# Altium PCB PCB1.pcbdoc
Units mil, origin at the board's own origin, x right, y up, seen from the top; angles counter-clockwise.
Board outline 1958.5 x 1420 mil, 2 copper layers (Top Layer, Bottom Layer); 4 components, 12 nets, 34 pads, 9 vias.
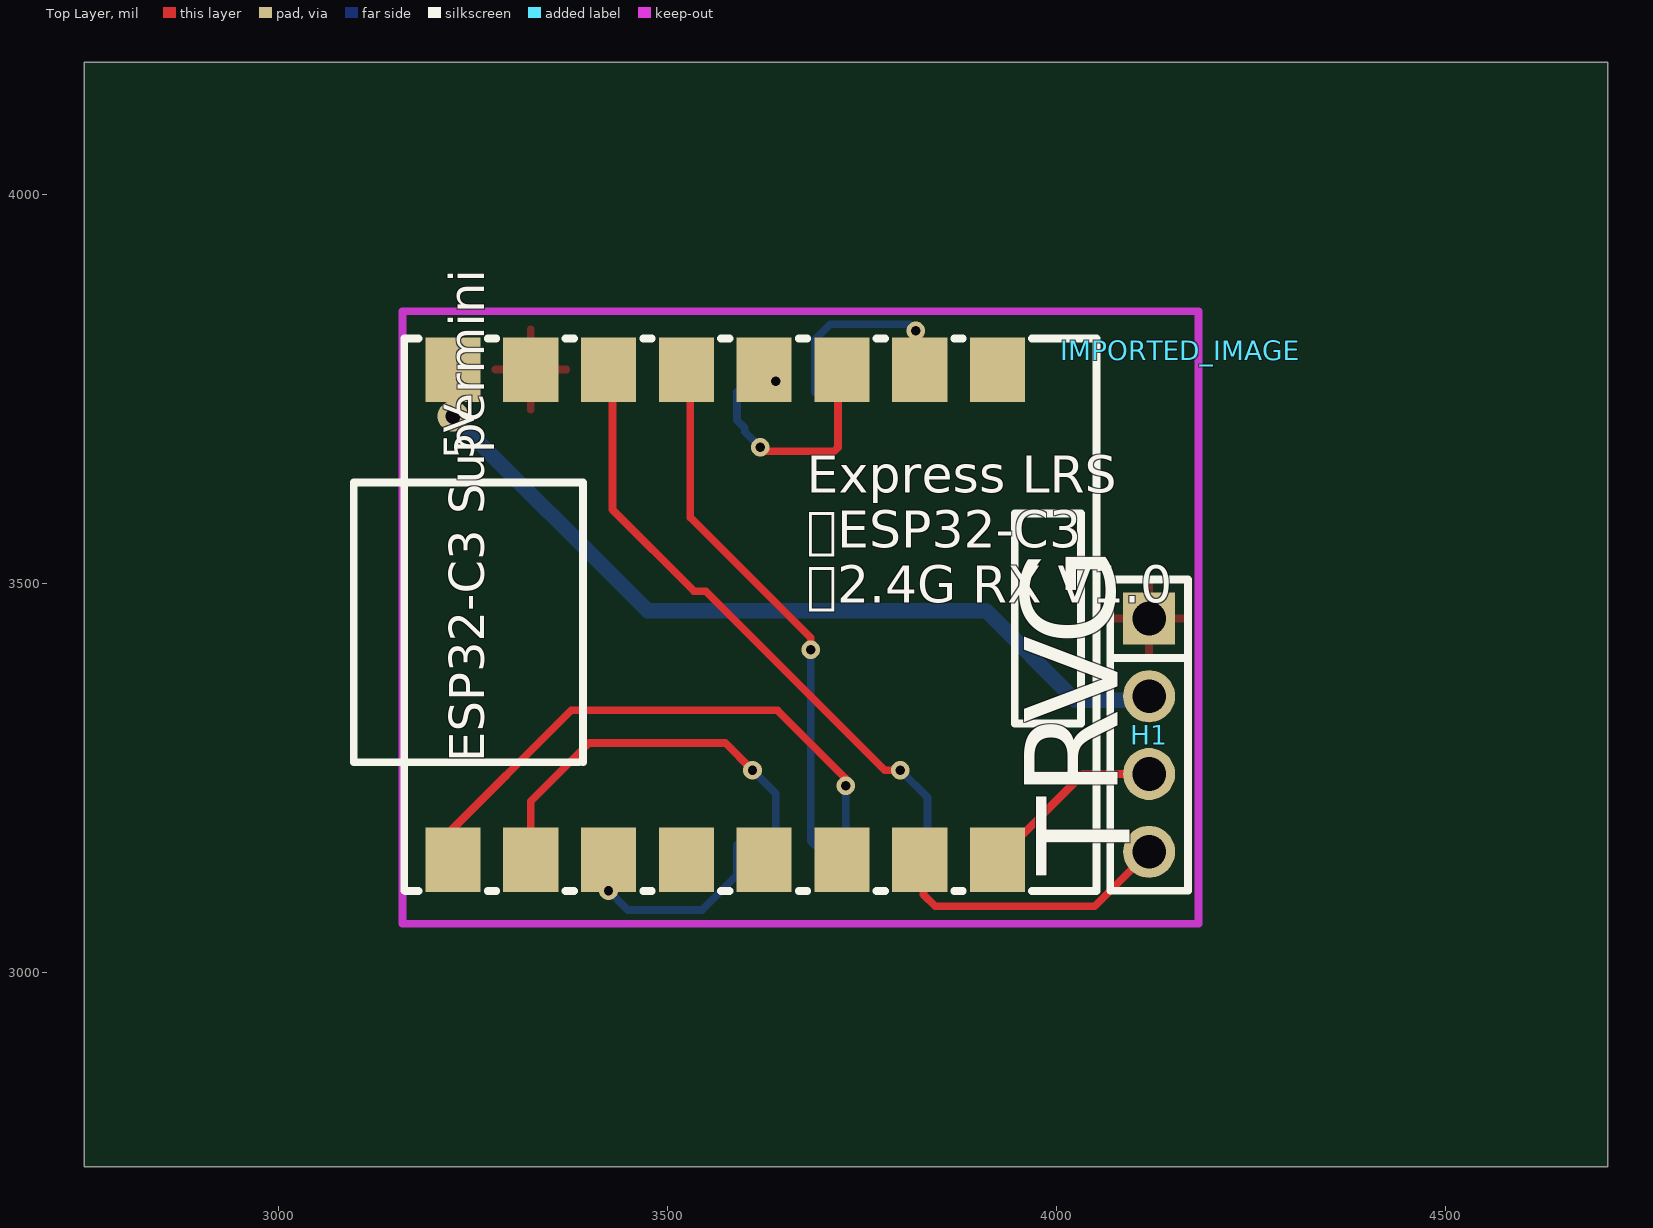
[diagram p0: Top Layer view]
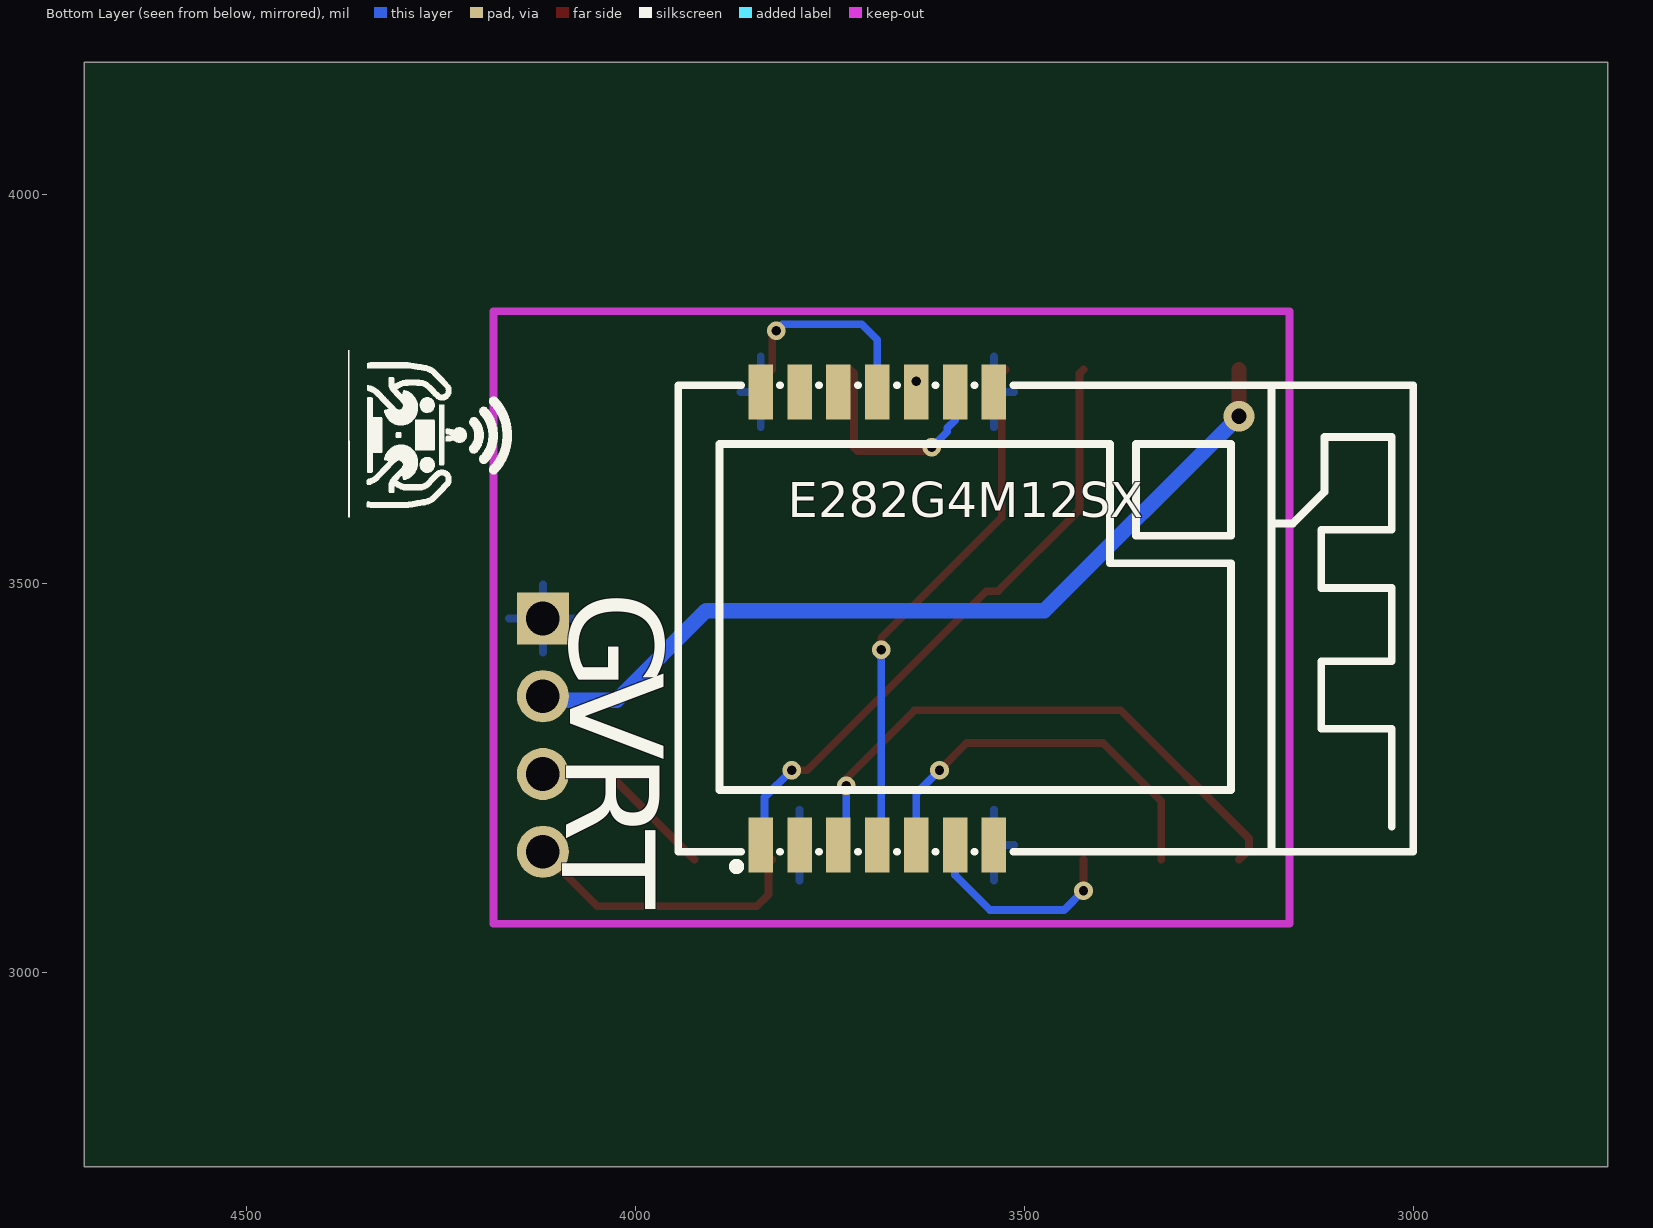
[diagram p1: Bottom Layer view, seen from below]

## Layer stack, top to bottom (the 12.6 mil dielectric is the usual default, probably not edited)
Top Layer: signal copper (thickness not stored)
Dielectric: dielectric 12.6, FR-4, Dk 4.8
Bottom Layer: signal copper (thickness not stored)

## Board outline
4708.5,2750 2750,2750 2750,4170 4708.5,4170

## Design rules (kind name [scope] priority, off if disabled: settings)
BoardOutlineClearance copperThickness1oz [All] p0: genericclearance=10 ignorepadtopadclearanceinfootprint=FALSE except(0: Arc-SplitContinuation Track-SplitContinuation SMDPad-SplitContinuation THPad-SplitContinuation Via-SplitContinuation Fill-SplitContinuation Poly-SplitContinuation Region-SplitContinuation Text-SplitContinuation; 6: Track-CutoutEdge SMDPad-CutoutEdge THPad-CutoutEdge Via-CutoutEdge Region-CutoutEdge; 11.8: Track-OutlineEdge SMDPad-OutlineEdge THPad-OutlineEdge Via-OutlineEdge Fill-OutlineEdge Region-OutlineEdge Poly-OutlineEdge Text-OutlineEdge Fill-CutoutEdge)
BoardOutlineClearance copperThickness2oz [All] p0: genericclearance=10 ignorepadtopadclearanceinfootprint=FALSE except(0: Arc-SplitContinuation Track-SplitContinuation SMDPad-SplitContinuation THPad-SplitContinuation Via-SplitContinuation Fill-SplitContinuation Poly-SplitContinuation Region-SplitContinuation Text-SplitContinuation; 6: Track-CutoutEdge SMDPad-CutoutEdge THPad-CutoutEdge Via-CutoutEdge Region-CutoutEdge; 11.8: Track-OutlineEdge SMDPad-OutlineEdge THPad-OutlineEdge Via-OutlineEdge Fill-OutlineEdge Region-OutlineEdge Poly-OutlineEdge Text-OutlineEdge Fill-CutoutEdge)
Clearance copperThickness1oz [(InNet('GND') OR InNet('$1N903') OR InNet('$1N951') OR InNet('$1N925') OR InNet('$1N893') OR InNet('$1N939') OR InNet('$1N882') OR InNet('$1N919') OR InNet('$1N1958') OR InNet('+5V') OR InNet('$1N1061') OR InNet('$1N2472'))] p1: gap=7 ignorepadtopadclearanceinfootprint=FALSE except(4: Track-Track; 6: Track-SMDPad SMDPad-SMDPad Track-THPad SMDPad-THPad THPad-THPad Track-Via SMDPad-Via THPad-Via Via-Via SMDPad-Fill THPad-Fill Via-Fill Fill-Fill Track-Region SMDPad-Region THPad-Region Via-Region Region-Region Track-Poly SMDPad-Poly THPad-Poly Via-Poly Fill-Poly Region-Poly Poly-Poly Track-Text SMDPad-Text THPad-Text Via-Text Fill-Text Region-Text Poly-Text Text-Text; 6.9: Track-Hole SMDPad-Hole THPad-Hole Via-Hole Fill-Hole Region-Hole Poly-Hole Text-Hole Sheet-Hole; 11.8: Track-Fill Fill-Region Track-Sheet SMDPad-Sheet THPad-Sheet Via-Sheet Fill-Sheet Region-Sheet Poly-Sheet Text-Sheet)
Clearance copperThickness2oz [All] p1: gap=7 ignorepadtopadclearanceinfootprint=FALSE except(6: Track-SMDPad SMDPad-SMDPad Track-THPad SMDPad-THPad THPad-THPad Track-Via SMDPad-Via THPad-Via Via-Via SMDPad-Fill THPad-Fill Via-Fill Fill-Fill Track-Region SMDPad-Region THPad-Region Via-Region Region-Region Track-Poly SMDPad-Poly THPad-Poly Via-Poly Fill-Poly Region-Poly Poly-Poly Track-Text SMDPad-Text THPad-Text Via-Text Fill-Text Region-Text Poly-Text Text-Text; 6.9: Track-Hole SMDPad-Hole THPad-Hole Via-Hole Fill-Hole Region-Hole Poly-Hole Text-Hole Sheet-Hole; 8: Track-Track; 11.8: Track-Fill Fill-Region Track-Sheet SMDPad-Sheet THPad-Sheet Via-Sheet Fill-Sheet Region-Sheet Poly-Sheet Text-Sheet)
DiffPairsRouting differentialPair [All] p1: maxuncoupledlength=10 minlimit=6 maxlimit=6 mostfreqgap=6 toplayer_minwidth=5 toplayer_prefwidth=10 toplayer_maxwidth=100 bottomlayer_minwidth=5 bottomlayer_prefwidth=10 bottomlayer_maxwidth=100
PasteMaskExpansion pasteMaskExpansion [All] p1: expansion=0
PlaneConnect innerPlane [All] p1: planeconnectstyle=Relief reliefexpansion=20 reliefentries=4 reliefconductorwidth=10 reliefairgap=10
PolygonConnect copperRegion [All] p1: connectstyle=Relief reliefentries=4 reliefconductorwidth=10 polygonreliefangle="90 Angle" airgapwidth=10
RoutingVias viaSize [All] p1: viastyle="Through Hole" holewidth=12.0078 minholewidth=11.811 maxholewidth=248.0314 width=24.0158 minwidth=19.685 maxwidth=393.7008
SolderMaskExpansion solderMaskExpansion [All] p1: useseparateexpansions=TRUE expansion=2 expansionbottom=2
Width copperThickness1oz [All] p1: maxlimit=100 minlimit=5 preferedwidth=10
Width copperThickness2oz [All] p1: maxlimit=100 minlimit=8 preferedwidth=10

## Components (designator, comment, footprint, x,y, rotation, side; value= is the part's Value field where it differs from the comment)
E282G4M12SX "E28-2G4M12S" WIRELM-SMD_E28-2G4M12S 3688.98,3455 r90 bottom
"ESP32-C3 Supermini" "ESP32C3-SuperMini" COMM-SMD_16P-L22.5-W18.0-P2.54-TL 3573.98,3460 r90 top
H1 "PZ254V-11-04P" HDR-TH_4P-P2.54-V-M 4118.98,3305 r270 top
IMPORTED_IMAGE "IMPORTED_IMAGE" IMPORTED_IMAGE 4158.98,3800 r0 top

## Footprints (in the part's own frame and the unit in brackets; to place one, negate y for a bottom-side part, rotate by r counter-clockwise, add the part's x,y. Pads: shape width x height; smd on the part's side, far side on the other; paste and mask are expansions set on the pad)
COMM-SMD_16P-L22.5-W18.0-P2.54-TL [mil]
  rect 82.76x70.94 smd: 1(-315,350) 2(-315,250) 3(-315,150) 4(-315,50) 5(-315,-50) 6(-315,-150) 7(-315,-250) 8(-315,-350) 9(315,-350) 10(315,-250) 11(315,-150) 12(315,-50) 13(315,50) 14(315,150) 15(315,250) 16(315,350)
  silkscreen extent -355,-477 355,478
HDR-TH_4P-P2.54-V-M [mm]
  rect 1.7x1.7 hole 1.1: 1(-3.81,0)
  round 1.7 hole 1.1: 2(-1.27,0) 3(1.27,0) 4(3.81,0)
  silkscreen extent -5.08,-1.27 5.08,1.27
IMPORTED_IMAGE [mil]
WIRELM-SMD_E28-2G4M12S [mm]
  rect 1.8x0.8 smd: 1(-7.4,3.81) 2(-7.4,2.54) 3(-7.4,1.27) 4(-7.4,0) 5(-7.4,-1.27) 6(-7.4,-2.54) 7(-7.4,-3.81) 8(7.4,-3.81) 9(7.4,-2.54) 10(7.4,-1.27) 11(7.4,0) 12(7.4,1.27) 13(7.4,2.54) 14(7.4,3.81)
  silkscreen extent -8.22,-17.5 7.62,6.5

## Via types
v1: diameter 24.02, hole 12.01, Top Layer to Bottom Layer, 8 vias
v2: diameter 39.37, hole 19.68, Top Layer to Bottom Layer, 1 vias

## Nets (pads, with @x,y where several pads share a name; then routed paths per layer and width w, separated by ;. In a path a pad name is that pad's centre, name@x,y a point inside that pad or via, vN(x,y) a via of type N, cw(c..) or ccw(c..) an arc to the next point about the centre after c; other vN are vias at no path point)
$1N882: "ESP32-C3 Supermini.12" E282G4M12SX.10 | length 13.7
  Bottom Layer w10: E282G4M12SX.10 v1(3638.98,3760)
$1N893: "ESP32-C3 Supermini.10" E282G4M12SX.11 | length 260.6
  Top Layer w10: v1(3818.98,3825) 3823.98,3820 3823.98,3775
  Bottom Layer w10: E282G4M12SX.11 3688.98,3813.19 3708.98,3833.19 3810.79,3833.19 v1(3818.98,3825)
$1N903: "ESP32-C3 Supermini.1" E282G4M12SX.3 | length 744.7
  Top Layer w10: 3223.98,3145 3211.05,3157.93 3211.05,3172.07 3376.05,3337.07 3641.05,3337.07 3728.98,3249.14 v1(3728.98,3240)
  Bottom Layer w10: v1(3728.98,3240) 3728.98,3173.66 E282G4M12SX.3
$1N919: "ESP32-C3 Supermini.13" E282G4M12SX.4 | length 679.7
  Top Layer w10: 3523.98,3775 3528.98,3770 3528.98,3585 3683.98,3430 v1(3683.98,3415)
  Bottom Layer w10: v1(3683.98,3415) 3683.98,3168.66 E282G4M12SX.4
$1N925: "ESP32-C3 Supermini.3" E282G4M12SX.6 | length 272.7
  Top Layer w10: v1(3423.98,3105) 3423.98,3145
  Bottom Layer w10: v1(3423.98,3105) 3448.98,3080 3543.98,3080 3588.98,3125 E282G4M12SX.6
$1N939: "ESP32-C3 Supermini.11" E282G4M12SX.9 | length 290
  Top Layer w10: v1(3618.98,3675) 3623.98,3670 3713.98,3670 3718.98,3675 3718.98,3770 3723.98,3775
  Bottom Layer w10: E282G4M12SX.9 3588.98,3710 3598.98,3700 3598.98,3695 v1(3618.98,3675)
$1N951: "ESP32-C3 Supermini.2" E282G4M12SX.5 | length 514.3
  Top Layer w10: 3323.98,3145 3323.98,3220 3398.98,3295 3573.98,3295 v1(3608.98,3260)
  Bottom Layer w10: v1(3608.98,3260) 3638.98,3230 E282G4M12SX.5
$1N1061: "ESP32-C3 Supermini.14" E282G4M12SX.1 | length 803.7
  Top Layer w10: 3423.98,3775 3428.98,3770 3428.98,3595 3533.98,3490 3548.98,3490 3778.98,3260 v1(3798.98,3260)
  Bottom Layer w10: v1(3798.98,3260) 3833.98,3225 3833.98,3168.66 E282G4M12SX.1
$1N1958: "ESP32-C3 Supermini.7" H1.4 | length 372.3
  Top Layer w10: 3823.98,3145 3828.98,3140 3828.98,3100 3843.98,3085 4048.98,3085 H1.4
$1N2472: "ESP32-C3 Supermini.8" H1.3 | length 240.6
  Top Layer w10: 3923.98,3145 4033.98,3255 H1.3
+5V: "ESP32-C3 Supermini.16" H1.2 | length 1108.3
  Top Layer w19.68: v2(3223.98,3715) 3223.98,3775
  Bottom Layer w19.68: v2(3223.98,3715) 3473.98,3465 3908.98,3465 4023.98,3350 4113.98,3350 H1.2
GND: "ESP32-C3 Supermini.15" E282G4M12SX.2 E282G4M12SX.7 E282G4M12SX.8 E282G4M12SX.14 H1.1
pads on no net: "ESP32-C3 Supermini.4" "ESP32-C3 Supermini.5" "ESP32-C3 Supermini.6" "ESP32-C3 Supermini.9" E282G4M12SX.12 E282G4M12SX.13

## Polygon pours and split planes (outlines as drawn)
GND on Bottom Layer (solid, remove dead copper, pour order 2): 3113.98,3905 4238.98,3905 4238.98,3020 3113.98,3020
GND on Top Layer (solid, remove dead copper, pour order 0): 3113.98,3920 4293.98,3920 4293.98,3000 3113.98,3000

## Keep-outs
Board Outline Layer:
  lines w10: 3158.98,3062.6 4182.6,3062.6 4182.6,3850 3158.98,3850 3158.98,3062.6

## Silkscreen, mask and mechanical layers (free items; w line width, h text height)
Top Silkscreen Layer:
  text "Express LRS /  ESP32-C3 /  2.4G RX V1.0" at 3678.98,3475 h47.24
  text "G" at 4073.98,3420 h120 r90
  text "V" at 4078.98,3320 h120 r90
  text "R" at 4078.98,3225 h120 r90
  text "T" at 4093.98,3125 h120 r90
Bottom Silkscreen Layer:
  text "G" at 4083.98,3490 h120 r90
  text "V" at 4083.98,3385 h120 r90
  text "R" at 4088.98,3282 h120 r90
  text "T" at 4093.98,3182 h120 r90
